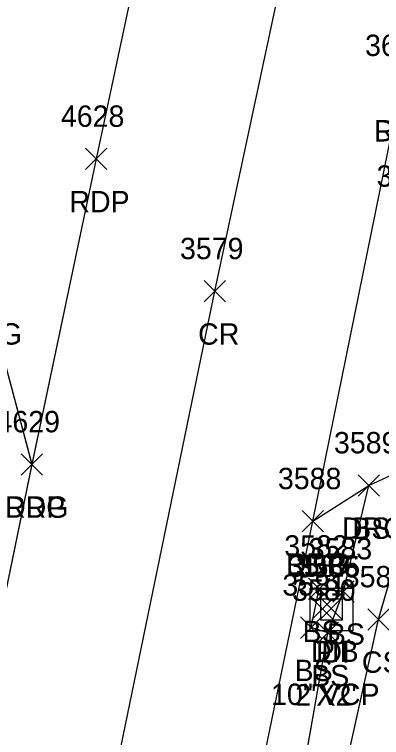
# Model space of a CAD drawing. Extents: x 1554668 to 1563881, y 831386 to 834374.
# Drawn here: x 1562428 to 1562462.4, y 833708.7 to 833776.4 of the extents above; entities that cross this region are included whole.
import ezdxf

# ---------------------------------------------------------------- set-up
doc = ezdxf.new("R2010")
doc.units = 0
for name, color, linetype in [('D_A', 7, 'Continuous'), ('D_C', 7, 'Continuous'), ('D_I', 7, 'Continuous'), ('D_TIC', 7, 'Continuous'), ('DS', 7, 'Continuous'), ('L_A', 7, 'Continuous'), ('L_I', 7, 'Continuous'), ('L_TIC', 7, 'Continuous'), ('LELB', 7, 'Continuous'), ('P_A', 7, 'Continuous'), ('P_I', 7, 'Continuous'), ('P_TIC', 7, 'Continuous'), ('PET', 7, 'Continuous'), ('PRC', 7, 'Continuous'), ('R_A', 7, 'Continuous'), ('R_I', 7, 'Continuous'), ('R_TIC', 7, 'Continuous'), ('RDG', 7, 'Continuous')]:
    doc.layers.add(name, color=color, linetype=linetype)

msp = doc.modelspace()

# ---------------------------------------------------------------- linework, layer by layer
at = {"layer": 'D_TIC'}
for points in [[(1562455.907, 833719.74), (1562457.907, 833721.74)], [(1562457.907, 833719.74), (1562455.907, 833721.74)], [(1562456.726, 833719.76), (1562458.726, 833721.76)], [(1562458.726, 833719.76), (1562456.726, 833721.76)]]:
    msp.add_lwpolyline(points, dxfattribs=at)
at = {"layer": 'DS'}
for p, q in [((1562455.734, 833722.686), (1562459.734, 833722.686)), ((1562455.734, 833718.686), (1562455.734, 833722.686)), ((1562459.734, 833722.686), (1562459.734, 833718.686)), ((1562456.734, 833719.686), (1562456.734, 833721.686)), ((1562456.734, 833721.686), (1562458.734, 833721.686)), ((1562458.734, 833721.686), (1562458.734, 833719.686)), ((1562457.74, 833720.688), (1562457.74, 833720.688)), ((1562457.74, 833720.688), (1562457.74, 833720.688)), ((1562458.734, 833719.686), (1562456.734, 833719.686)), ((1562459.734, 833718.686), (1562455.734, 833718.686))]:
    msp.add_line(p, q, dxfattribs=at)
at = {"layer": 'L_TIC'}
for points in [[(1562460.241, 833731.286), (1562462.241, 833733.286)], [(1562462.241, 833731.286), (1562460.241, 833733.286)], [(1562455.585, 833721.621), (1562457.585, 833723.621)], [(1562457.585, 833721.621), (1562455.585, 833723.621)], [(1562457.865, 833721.371), (1562459.865, 833723.371)], [(1562459.865, 833721.371), (1562457.865, 833723.371)], [(1562457.865, 833721.371), (1562459.865, 833723.371)], [(1562459.865, 833721.371), (1562457.865, 833723.371)], [(1562461.15, 833718.752), (1562463.15, 833720.752)], [(1562463.15, 833718.752), (1562461.15, 833720.752)], [(1562454.836, 833717.976), (1562456.836, 833719.976)], [(1562456.836, 833717.976), (1562454.836, 833719.976)], [(1562456.398, 833717.487), (1562458.398, 833719.487)], [(1562458.398, 833717.487), (1562456.398, 833719.487)], [(1562456.398, 833717.487), (1562458.398, 833719.487)], [(1562458.398, 833717.487), (1562456.398, 833719.487)]]:
    msp.add_lwpolyline(points, dxfattribs=at)
at = {"layer": 'LELB'}
for points in [[(1562436.59, 833611.09), (1562443.345, 833639.966), (1562457.073, 833696.898), (1562462.15, 833719.752), (1562466.499, 833734.719)], [(1562436.592, 833611.1), (1562443.347, 833639.973), (1562457.073, 833696.905), (1562462.151, 833719.759), (1562466.499, 833734.722)], [(1562436.592, 833611.1), (1562443.347, 833639.973), (1562457.073, 833696.905), (1562462.151, 833719.759), (1562466.499, 833734.722)], [(1562436.592, 833611.1), (1562443.347, 833639.973), (1562457.073, 833696.905), (1562462.151, 833719.759), (1562466.499, 833734.722)], [(1562437.602, 833600.054), (1562436.59, 833611.09), (1562441.078, 833640.693), (1562453.763, 833697.919), (1562457.398, 833718.487), (1562455.836, 833718.976), (1562456.585, 833722.621), (1562458.865, 833722.371), (1562461.241, 833732.286)], [(1562437.602, 833600.057), (1562436.592, 833611.1), (1562441.078, 833640.699), (1562453.764, 833697.926), (1562457.399, 833718.494), (1562455.837, 833718.985), (1562456.586, 833722.627), (1562458.866, 833722.38), (1562461.241, 833732.288)], [(1562437.602, 833600.057), (1562436.592, 833611.1), (1562441.078, 833640.699), (1562453.764, 833697.926), (1562457.399, 833718.494), (1562455.837, 833718.985), (1562456.586, 833722.627), (1562458.866, 833722.38), (1562461.241, 833732.288)], [(1562437.602, 833600.057), (1562436.592, 833611.1), (1562441.078, 833640.699), (1562453.764, 833697.926), (1562457.399, 833718.494), (1562455.837, 833718.985), (1562456.586, 833722.627), (1562458.866, 833722.38), (1562461.241, 833732.288)], [(1562457.398, 833718.487), (1562458.865, 833722.371)], [(1562457.399, 833718.494), (1562458.866, 833722.38)], [(1562457.399, 833718.494), (1562458.866, 833722.38)], [(1562457.399, 833718.494), (1562458.866, 833722.38)]]:
    msp.add_lwpolyline(points, dxfattribs=at)
at = {"layer": 'P_TIC'}
for points in [[(1562434.697, 833761.843), (1562436.697, 833763.843)], [(1562436.697, 833761.843), (1562434.697, 833763.843)], [(1562445.815, 833749.458), (1562447.815, 833751.458)], [(1562447.815, 833749.458), (1562445.815, 833751.458)], [(1562428.671, 833733.255), (1562430.671, 833735.255)], [(1562430.671, 833733.255), (1562428.671, 833735.255)], [(1562454.981, 833727.934), (1562456.981, 833729.934)], [(1562456.981, 833727.934), (1562454.981, 833729.934)]]:
    msp.add_lwpolyline(points, dxfattribs=at)
at = {"layer": 'PET'}
for points in [[(1562390.311, 833375.989), (1562393.977, 833397.67), (1562399.624, 833430.723), (1562404.076, 833456.64), (1562408.479, 833482.044), (1562418.419, 833535.55), (1562424.853, 833574.142), (1562431.347, 833605.093), (1562438.205, 833641.603), (1562449.823, 833698.96), (1562455.982, 833728.945), (1562464.252, 833769.476), (1562472.427, 833806.927), (1562484.773, 833859.846), (1562495.065, 833901.936), (1562505.742, 833945.836), (1562515.589, 833982.411), (1562522.272, 834008.538), (1562529.881, 834035.713), (1562547.387, 834091.493), (1562561.695, 834132.946), (1562566.268, 834145.816)], [(1562390.311, 833375.989), (1562393.977, 833397.67), (1562399.624, 833430.723), (1562404.076, 833456.64), (1562408.479, 833482.044), (1562418.419, 833535.55), (1562424.853, 833574.142), (1562431.347, 833605.093), (1562438.205, 833641.603), (1562449.823, 833698.96), (1562455.982, 833728.945), (1562464.252, 833769.476), (1562472.427, 833806.927), (1562484.773, 833859.846), (1562495.065, 833901.936), (1562505.742, 833945.836), (1562515.589, 833982.411), (1562522.272, 834008.538), (1562529.881, 834035.713), (1562547.387, 834091.493), (1562561.695, 834132.946), (1562566.268, 834145.816)], [(1562390.311, 833375.989), (1562393.977, 833397.67), (1562399.624, 833430.723), (1562404.076, 833456.64), (1562408.479, 833482.044), (1562418.419, 833535.55), (1562424.853, 833574.142), (1562431.347, 833605.093), (1562438.205, 833641.603), (1562449.823, 833698.96), (1562455.982, 833728.945), (1562464.252, 833769.476), (1562472.427, 833806.927), (1562484.773, 833859.846), (1562495.065, 833901.936), (1562505.742, 833945.836), (1562515.589, 833982.411), (1562522.272, 834008.538), (1562529.881, 834035.713), (1562547.387, 834091.493), (1562561.695, 834132.946), (1562566.268, 834145.816)], [(1562390.312, 833375.983), (1562393.977, 833397.668), (1562399.627, 833430.715), (1562404.077, 833456.635), (1562408.483, 833482.042), (1562418.422, 833535.549), (1562424.854, 833574.14), (1562431.348, 833605.09), (1562438.2, 833641.597), (1562449.823, 833698.953), (1562455.981, 833728.934), (1562464.252, 833769.469), (1562472.429, 833806.92), (1562484.77, 833859.84), (1562495.065, 833901.93), (1562505.741, 833945.826), (1562515.584, 833982.407), (1562522.267, 834008.535), (1562529.877, 834035.701), (1562547.383, 834091.48), (1562561.691, 834132.936), (1562566.264, 834145.807)], [(1562446.514, 833813.563), (1562435.7, 833762.854), (1562429.669, 833734.264), (1562422.437, 833699.227), (1562413.341, 833652.592), (1562406.134, 833614.879), (1562402.03, 833593.791), (1562399.545, 833580.082), (1562389.601, 833524.029), (1562386.342, 833504.136), (1562384.709, 833497.669), (1562380.24, 833469.601), (1562374.637, 833437.636), (1562367.889, 833393.469), (1562360.289, 833352.08)], [(1562446.514, 833813.563), (1562435.7, 833762.854), (1562429.669, 833734.264), (1562422.437, 833699.227), (1562413.341, 833652.592), (1562406.134, 833614.879), (1562402.03, 833593.791), (1562399.545, 833580.082), (1562389.601, 833524.029), (1562386.342, 833504.136), (1562384.709, 833497.669), (1562380.24, 833469.601), (1562374.637, 833437.636), (1562367.889, 833393.469), (1562360.289, 833352.08)], [(1562446.514, 833813.563), (1562435.7, 833762.854), (1562429.669, 833734.264), (1562422.437, 833699.227), (1562413.341, 833652.592), (1562406.134, 833614.879), (1562402.03, 833593.791), (1562399.545, 833580.082), (1562389.601, 833524.029), (1562386.342, 833504.136), (1562384.709, 833497.669), (1562380.24, 833469.601), (1562374.637, 833437.636), (1562367.889, 833393.469), (1562360.289, 833352.08)], [(1562446.513, 833813.556), (1562435.697, 833762.843), (1562429.671, 833734.255), (1562422.435, 833699.223), (1562413.341, 833652.586), (1562406.134, 833614.874), (1562402.03, 833593.785), (1562399.545, 833580.078), (1562389.599, 833524.021), (1562386.34, 833504.127), (1562384.71, 833497.666), (1562380.238, 833469.596), (1562374.637, 833437.628), (1562367.889, 833393.463), (1562360.289, 833352.078)]]:
    msp.add_lwpolyline(points, dxfattribs=at)
at = {"layer": 'PRC'}
for points in [[(1562374.328, 833358.788), (1562379.819, 833391.645), (1562386.805, 833432.043), (1562394.132, 833473.552), (1562401.52, 833515.146), (1562408.626, 833554.57), (1562418.317, 833607.158), (1562425.122, 833644.153), (1562437.129, 833703.517), (1562446.816, 833750.468), (1562457.117, 833798.654), (1562467.75, 833845.524), (1562476.843, 833883.646), (1562492.325, 833945.243), (1562502.519, 833985.558), (1562516.732, 834038.229), (1562535.447, 834096.625), (1562549.682, 834139.255), (1562553.417, 834150.261)], [(1562374.328, 833358.788), (1562379.819, 833391.645), (1562386.805, 833432.043), (1562394.132, 833473.552), (1562401.52, 833515.146), (1562408.626, 833554.57), (1562418.317, 833607.158), (1562425.122, 833644.153), (1562437.129, 833703.517), (1562446.816, 833750.468), (1562457.117, 833798.654), (1562467.75, 833845.524), (1562476.843, 833883.646), (1562492.325, 833945.243), (1562502.519, 833985.558), (1562516.732, 834038.229), (1562535.447, 834096.625), (1562549.682, 834139.255), (1562553.417, 834150.261)], [(1562374.328, 833358.788), (1562379.819, 833391.645), (1562386.805, 833432.043), (1562394.132, 833473.552), (1562401.52, 833515.146), (1562408.626, 833554.57), (1562418.317, 833607.158), (1562425.122, 833644.153), (1562437.129, 833703.517), (1562446.816, 833750.468), (1562457.117, 833798.654), (1562467.75, 833845.524), (1562476.843, 833883.646), (1562492.325, 833945.243), (1562502.519, 833985.558), (1562516.732, 834038.229), (1562535.447, 834096.625), (1562549.682, 834139.255), (1562553.417, 834150.261)], [(1562374.328, 833358.78), (1562379.82, 833391.635), (1562386.804, 833432.041), (1562394.133, 833473.548), (1562401.522, 833515.144), (1562408.625, 833554.563), (1562418.32, 833607.155), (1562425.125, 833644.147), (1562437.128, 833703.511), (1562446.815, 833750.458), (1562457.117, 833798.648), (1562467.753, 833845.523), (1562476.843, 833883.643), (1562492.321, 833945.235), (1562502.515, 833985.553), (1562516.728, 834038.221), (1562535.444, 834096.612), (1562549.678, 834139.252), (1562553.413, 834150.251)]]:
    msp.add_lwpolyline(points, dxfattribs=at)
at = {"layer": 'R_TIC'}
for points in [[(1562428.671, 833733.255), (1562430.671, 833735.255)], [(1562430.671, 833733.255), (1562428.671, 833735.255)], [(1562460.241, 833731.286), (1562462.241, 833733.286)], [(1562462.241, 833731.286), (1562460.241, 833733.286)], [(1562454.981, 833727.934), (1562456.981, 833729.934)], [(1562456.981, 833727.934), (1562454.981, 833729.934)]]:
    msp.add_lwpolyline(points, dxfattribs=at)
at = {"layer": 'RDG'}
for points in [[(1562446.514, 833813.563), (1562443.872, 833811.177), (1562440.454, 833805.407), (1562432.393, 833800.653), (1562424.083, 833800.435), (1562417.273, 833767.263), (1562421.889, 833758.153), (1562425.326, 833750.474), (1562429.669, 833734.264)], [(1562446.514, 833813.563), (1562443.872, 833811.177), (1562440.454, 833805.407), (1562432.393, 833800.653), (1562424.083, 833800.435), (1562417.273, 833767.263), (1562421.889, 833758.153), (1562425.326, 833750.474), (1562429.669, 833734.264)], [(1562446.514, 833813.563), (1562443.872, 833811.177), (1562440.454, 833805.407), (1562432.393, 833800.653), (1562424.083, 833800.435), (1562417.273, 833767.263), (1562421.889, 833758.153), (1562425.326, 833750.474), (1562429.669, 833734.264)], [(1562446.513, 833813.556), (1562443.872, 833811.172), (1562440.453, 833805.4), (1562432.393, 833800.647), (1562424.084, 833800.427), (1562417.274, 833767.254), (1562421.893, 833758.146), (1562425.324, 833750.465), (1562429.671, 833734.255)], [(1562455.981, 833728.934), (1562461.241, 833732.286), (1562466.499, 833734.719), (1562476.618, 833737.851), (1562488.15, 833738.174), (1562515.936, 833741.241)], [(1562455.982, 833728.945), (1562461.241, 833732.288), (1562466.499, 833734.722), (1562476.617, 833737.855), (1562488.149, 833738.176), (1562515.939, 833741.251)], [(1562455.982, 833728.945), (1562461.241, 833732.288), (1562466.499, 833734.722), (1562476.617, 833737.855), (1562488.149, 833738.176), (1562515.939, 833741.251)], [(1562455.982, 833728.945), (1562461.241, 833732.288), (1562466.499, 833734.722), (1562476.617, 833737.855), (1562488.149, 833738.176), (1562515.939, 833741.251)]]:
    msp.add_lwpolyline(points, dxfattribs=at)

# ---------------------------------------------------------------- texts
at = {"layer": 'D_A'}
for s, p in [('DIB', (1562455.828, 833715.76)), ('P', (1562456.285, 833715.74)), ('DI', (1562456.795, 833715.688))]:
    msp.add_text(s, height=2, dxfattribs=at).set_placement(p)
at = {"layer": 'D_C'}
for s, p in [('10" VCP', (1562452.08, 833711.74)), ("2'X2'", (1562454.338, 833711.688))]:
    msp.add_text(s, height=2, dxfattribs=at).set_placement(p)
at = {"layer": 'D_I'}
for s, p in [('3587', (1562453.647, 833723.74)), ('3586', (1562454.411, 833723.76)), ('3585', (1562454.48, 833723.688))]:
    msp.add_text(s, height=2, dxfattribs=at).set_placement(p)
at = {"layer": 'L_A'}
for s, p in [('BS', (1562459.682, 833727.286)), ('BS', (1562455.026, 833717.621)), ('BS', (1562457.306, 833717.371)), ('BS', (1562457.306, 833717.371)), ('CS', (1562460.591, 833714.752)), ('BS', (1562454.277, 833713.976)), ('BS', (1562455.839, 833713.487)), ('BS', (1562455.839, 833713.487))]:
    msp.add_text(s, height=2, dxfattribs=at).set_placement(p)
at = {"layer": 'L_I'}
for s, p in [('3589', (1562457.973, 833735.286)), ('3582', (1562453.325, 833725.621)), ('3583', (1562455.605, 833725.371)), ('3583', (1562455.605, 833725.371)), ('3584', (1562458.89, 833722.752)), ('3581', (1562453.143, 833721.976)), ('3580', (1562454.052, 833721.487)), ('3580', (1562454.052, 833721.487))]:
    msp.add_text(s, height=2, dxfattribs=at).set_placement(p)
at = {"layer": 'P_A'}
for s, p in [('RDP', (1562461.74, 833764.469)), ('RDP', (1562433.186, 833757.843)), ('CR', (1562445.249, 833745.458)), ('RDP', (1562427.159, 833729.255)), ('RDP', (1562453.469, 833723.934))]:
    msp.add_text(s, height=2, dxfattribs=at).set_placement(p)
at = {"layer": 'P_I'}
for s, p in [('3636', (1562460.889, 833772.469)), ('4628', (1562432.39, 833765.843)), ('3579', (1562443.548, 833753.458)), ('4629', (1562426.356, 833737.255)), ('3588', (1562452.721, 833731.934))]:
    msp.add_text(s, height=2, dxfattribs=at).set_placement(p)
at = {"layer": 'R_A'}
for s, p in [('DRP', (1562461.74, 833764.469)), ('DRG', (1562422.812, 833745.465)), ('DRG', (1562427.159, 833729.255)), ('DRG', (1562458.729, 833727.286)), ('DRG', (1562453.469, 833723.934))]:
    msp.add_text(s, height=2, dxfattribs=at).set_placement(p)
at = {"layer": 'R_I'}
for s, p in [('3636', (1562460.889, 833772.469)), ('3635', (1562461.974, 833760.242)), ('4629', (1562426.356, 833737.255)), ('3589', (1562457.973, 833735.286)), ('3588', (1562452.721, 833731.934))]:
    msp.add_text(s, height=2, dxfattribs=at).set_placement(p)

doc.saveas('drawing.dxf')
